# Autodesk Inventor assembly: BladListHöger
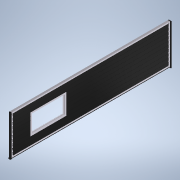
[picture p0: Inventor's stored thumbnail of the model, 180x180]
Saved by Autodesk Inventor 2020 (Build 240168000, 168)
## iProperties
Created: 2019-06
Part Number: BladListHöger
Document SubType Name: Assembly
Designer: cl
Author: cl
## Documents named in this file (6)
- G:\AutoCad\Carl Lund\4-delad\BladListHöger.iam
- G:\AutoCad\Carl Lund\4-delad\Blad.ipt
- G:\AutoCad\Carl Lund\4-delad\AluKarmBlad.ipt
- G:\AutoCad\Carl Lund\4-delad\4-delad.iam
- G:\AutoCad\Carl Lund\4-delad\Gummilist1.ipt
- G:\AutoCad\Carl Lund\4-delad\AluFönster.ipt
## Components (4 placed, 4 different names)
1. Blad:1 — Flush:1, Flush:2, Flush:4, Flush:14
2. AluKarmBlad:1 — Flush:1, Flush:2, Flush:3
3. Gummilist1:1 — Flush:3
4. AluFönster:1 — Flush:4, Flush:14
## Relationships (5: Flush 5)
- Flush:1: Blad:1 ↔ AluKarmBlad:1
- Flush:2: Blad:1 ↔ AluKarmBlad:1
- Flush:3: AluKarmBlad:1 ↔ Gummilist1:1
- Flush:4: Blad:1 ↔ AluFönster:1
- Flush:14: Blad:1 ↔ AluFönster:1
## Named parameters: BladBredd = 987.5 mm
